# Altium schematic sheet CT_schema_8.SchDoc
size 274 x 160 mm
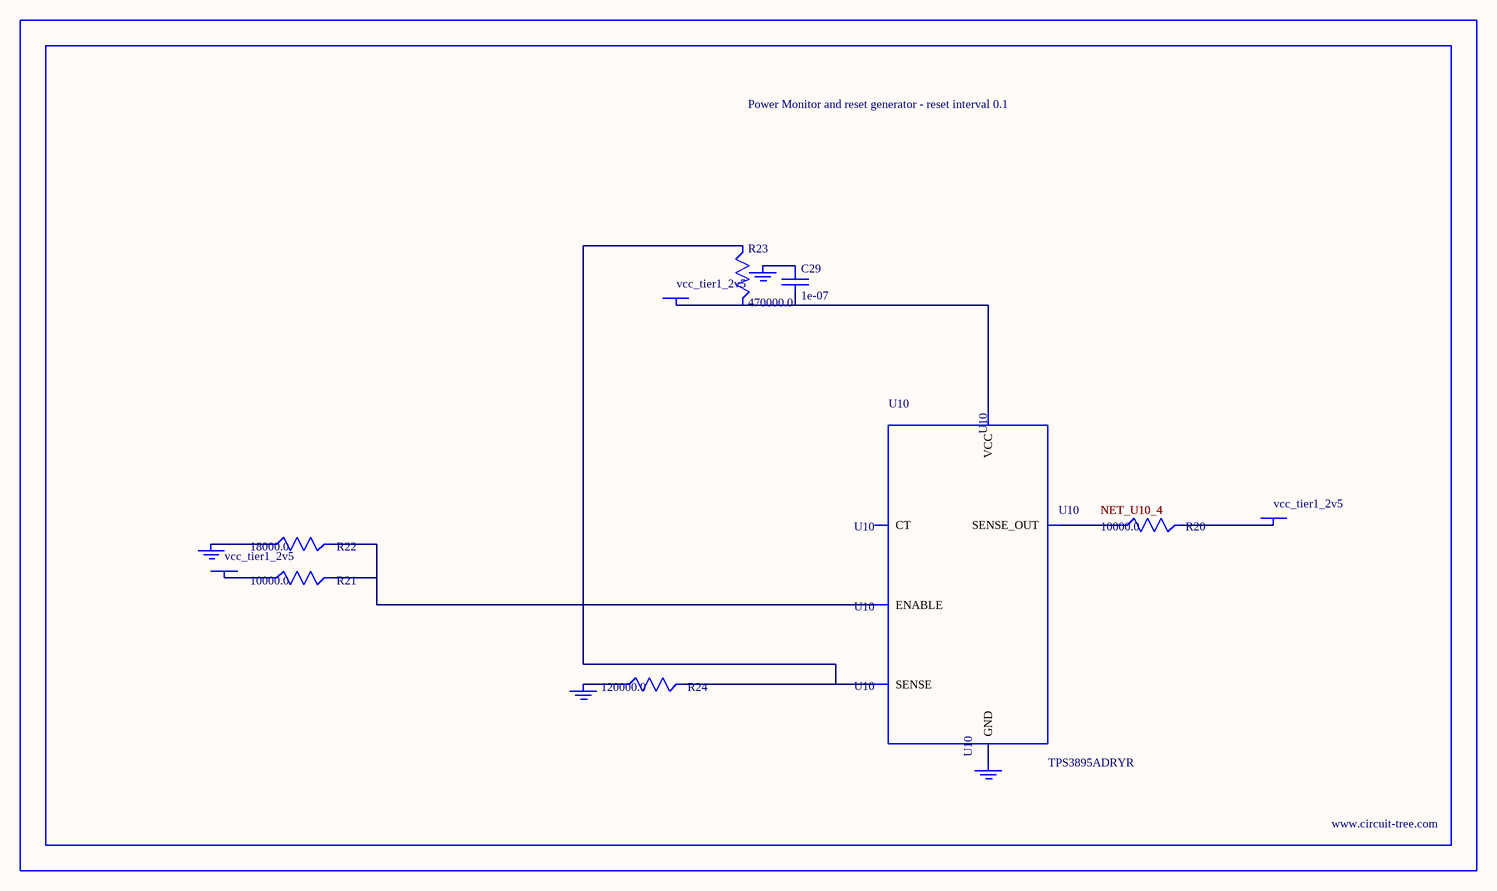
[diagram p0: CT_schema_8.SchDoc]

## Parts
BORDER7  (no value)
C29  1e-07  [C0402]
GND_INSTANCE_7_0  (no value)
GND_INSTANCE_7_1  (no value)
GND_INSTANCE_7_2  (no value)
GND_INSTANCE_7_3  (no value)
POWER_INSTANCE_7_0  vcc_tier1_2v5
POWER_INSTANCE_7_1  vcc_tier1_2v5
POWER_INSTANCE_7_2  vcc_tier1_2v5
R20  10000.0  [R0603]
R21  10000.0  [R0603]
R22  18000.0  [R0603]
R23  470000.0  [R0603]
R24  120000.0  [R0603]
U10  TPS3895ADRYR  [SON-6]

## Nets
NetC29_1: C29.1 GND_INSTANCE_7_2.0(GND)
NetC29_2: C29.2 POWER_INSTANCE_7_2.0(PWR) R23.2 U10.6(VCC)
NetGND_INSTANCE_7_0_0: GND_INSTANCE_7_0.0(GND) R22.1
NetGND_INSTANCE_7_1_0: GND_INSTANCE_7_1.0(GND) R24.1
NetGND_INSTANCE_7_3_0: GND_INSTANCE_7_3.0(GND) U10.2(GND)
NetPOWER_INSTANCE_7_0_0: POWER_INSTANCE_7_0.0(PWR) R21.1
NetPOWER_INSTANCE_7_1_0: POWER_INSTANCE_7_1.0(PWR) R20.2
NetR20_1: R20.1 U10.4(SENSE_OUT)
NetR21_2: R21.2 R22.2 U10.1(ENABLE)
NetR23_1: R23.1 R24.2 U10.3(SENSE)

Not connected (* = marked no-connect by the designer): U10 5(CT)

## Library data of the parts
BORDER7 = BORDER_PAGE7
C29 = C0402C104K3RACTU
GND_INSTANCE_7_0-GND_INSTANCE_7_3 = GND
POWER_INSTANCE_7_0-POWER_INSTANCE_7_2 = PWR
R20 R21 = RC0603JR-0710KL
R22 = RC0603JR-0718KL
R23 = RC0603JR-07470KL
R24 = RC0603JR-07120KL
